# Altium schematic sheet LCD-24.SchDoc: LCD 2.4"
size A4; Date: Not used; ApprovedBy: Not used; CheckedBy: Not used; Author: Not used; CompanyName: STMicroelectronics; DrawnBy: Not used; Engineer: Not used; Organization: Not used; Address1: Not used; Address2: Not used; Address3: Not used; Address4: Not used; Revision: Not used; SheetNumber: 6; SheetTotal: 8
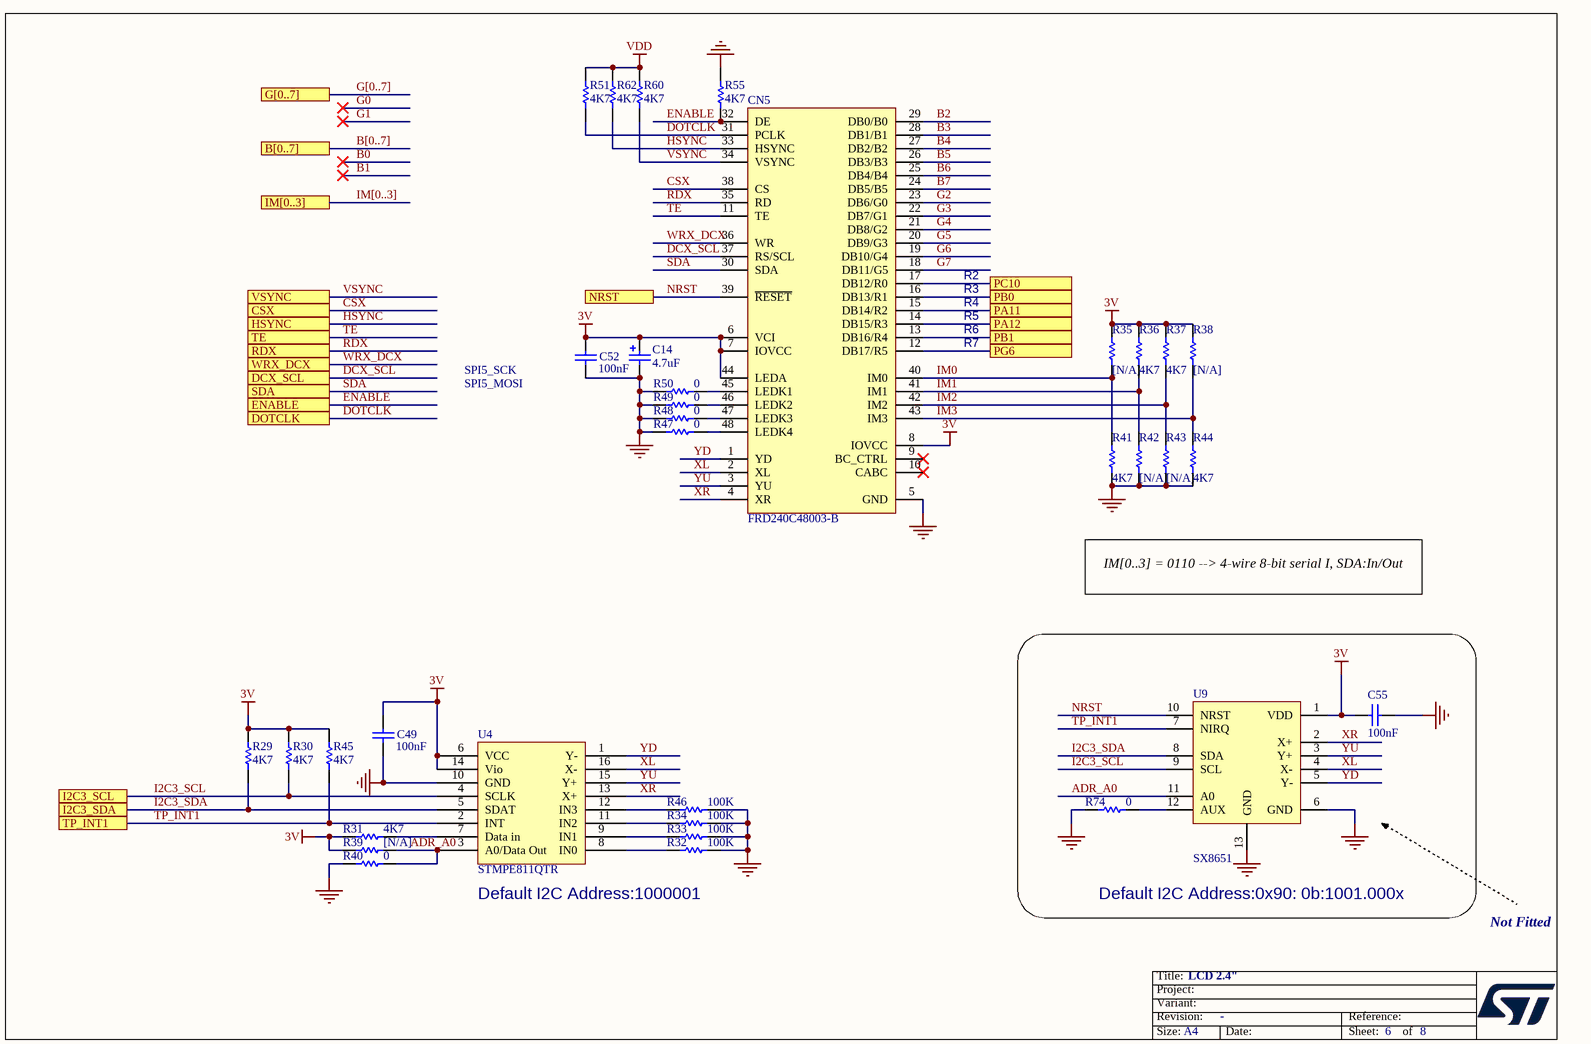
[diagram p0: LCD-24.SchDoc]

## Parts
C14  4.7uF  [TAN-A]
C49  100nF  [0402C]
C52  100nF  [0402C]
C55  100nF  [0402C]
CN5  FRD240C48003-B  [LCD_FRIDA_FRD240C48003-B]
R29  4K7  [0402R]
R30  4K7  [0402R]
R31  4K7  [0402R]
R32  100K  [0402R]
R33  100K  [0402R]
R34  100K  [0402R]
R35  [N/A]  [0402R]
R36  4K7  [0402R]
R37  4K7  [0402R]
R38  [N/A]  [0402R]
R39  [N/A]  [0402R]
R40  0  [0402R]
R41  4K7  [0402R]
R42  [N/A]  [0402R]
R43  [N/A]  [0402R]
R44  4K7  [0402R]
R45  4K7  [0402R]
R46  100K  [0402R]
R47  0  [0603R]
R48  0  [0603R]
R49  0  [0603R]
R50  0  [0603R]
R51  4K7  [0402R]
R55  4K7  [0402R]
R60  4K7  [0402R]
R62  4K7  [0402R]
R74  0  [0402R]
U4  STMPE811QTR  [QFN16_3X3]
U9  SX8651  [ICC_DFN12-EPAD_3X3_P045]

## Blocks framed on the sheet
Default I2C Address:0x90: 0b:1001.000x: C55 R74 U9

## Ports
B[0..7], CSX, DCX_SCL, DOTCLK, ENABLE, G[0..7], HSYNC, I2C3_SCL, I2C3_SDA, IM[0..3], NRST, PA11, PA12, PB0, PB1, PC10, PG6, RDX, SDA, TE, TP_INT1, VSYNC, WRX_DCX

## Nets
3V: C14.1 C49.2 C52.2 C55.1 CN5.6(VCI) CN5.7(IOVCC) CN5.8(IOVCC) CN5.44(LEDA) R29.2 R30.2 R31.1 R35.2 R36.2 R37.2 R38.2 R39.1 R45.2 U4.6(VCC) U4.14(Vio) U9.1(VDD)
GND: C14.2 C49.1 C52.1 C55.2 CN5.5(GND) R32.2 R33.2 R34.2 R40.1 R41.1 R42.1 R43.1 R44.1 R46.2 R47.1 R48.1 R49.1 R50.1 R55.2 R74.1 U4.10(GND) U9.6(GND) U9.13(GND)
VDD: R51.2 R60.2 R62.2
ADR_A0: R39.2 R40.2 U4.3(A0/Data_Out) U9.11(A0)
B2: CN5.29(DB0/B0)
B3: CN5.28(DB1/B1)
B4: CN5.27(DB2/B2)
B5: CN5.26(DB3/B3)
B6: CN5.25(DB4/B4)
B7: CN5.24(DB5/B5)
CSX: CN5.38(CS) ; port CSX
DCX_SCL: CN5.37(RS/SCL) ; port DCX_SCL
DOTCLK: CN5.31(PCLK) R51.1 ; port DOTCLK
ENABLE: CN5.32(DE) R55.1 ; port ENABLE
G2: CN5.23(DB6/G0)
G3: CN5.22(DB7/G1)
G4: CN5.21(DB8/G2)
G5: CN5.20(DB9/G3)
G6: CN5.19(DB10/G4)
G7: CN5.18(DB11/G5)
HSYNC: CN5.33(HSYNC) R62.1 ; port HSYNC
I2C3_SCL: R30.1 U4.4(SCLK) U9.9(SCL) ; port I2C3_SCL
I2C3_SDA: R29.1 U4.5(SDAT) U9.8(SDA) ; port I2C3_SDA
IM0: CN5.40(IM0) R35.1 R41.2
IM1: CN5.41(IM1) R36.1 R42.2
IM2: CN5.42(IM2) R37.1 R43.2
IM3: CN5.43(IM3) R38.1 R44.2
NRST: CN5.39(~{RESET}) U9.10(NRST) ; port NRST
PA11: CN5.15(DB14/R2) ; port PA11
PA12: CN5.14(DB15/R3) ; port PA12
PB0: CN5.16(DB13/R1) ; port PB0
PB1: CN5.13(DB16/R4) ; port PB1
PC10: CN5.17(DB12/R0) ; port PC10
PG6: CN5.12(DB17/R5) ; port PG6
RDX: CN5.35(RD) ; port RDX
SDA: CN5.30(SDA) ; port SDA
TE: CN5.11(TE) ; port TE
TP_INT1: R45.1 U4.2(INT) U9.7(NIRQ) ; port TP_INT1
VSYNC: CN5.34(VSYNC) R60.1 ; port VSYNC
WRX_DCX: CN5.36(WR) ; port WRX_DCX
XL: CN5.2(XL) U4.16(X-) U9.4(X-)
XR: CN5.4(XR) U4.13(X+) U9.2(X+)
YD: CN5.1(YD) U4.1(Y-) U9.5(Y-)
YU: CN5.3(YU) U4.15(Y+) U9.3(Y+)
NetCN5_45: CN5.45(LEDK1) R50.2
NetCN5_46: CN5.46(LEDK2) R49.2
NetCN5_47: CN5.47(LEDK3) R48.2
NetCN5_48: CN5.48(LEDK4) R47.2
NetR31_2: R31.2 U4.7(Data_in)
NetR32_1: R32.1 U4.8(IN0)
NetR33_1: R33.1 U4.9(IN1)
NetR34_1: R34.1 U4.11(IN2)
NetR46_1: R46.1 U4.12(IN3)
NetR74_2: R74.2 U9.12(AUX)

Not connected (* = marked no-connect by the designer): CN5 9(BC_CTRL)* 10(CABC)*

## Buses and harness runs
bus B[0..7] = port B[0..7]
bus G[0..7] = port G[0..7]
bus IM[0..3] = port IM[0..3]

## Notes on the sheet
- R4
- R5
- R3
- R2
- SPI5_MOSI
- SPI5_SCK
- R6
- R7
- IM[0..3] = 0110 --> 4-wire 8-bit serial I, SDA:In/Out
- Default I2C Address:1000001
- Not Fitted

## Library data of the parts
C14 = Cap Pol1: Polarized Capacitor (Radial); Value: 100pF
C49 C52 = Capacitor_ST: Capacitor 0402 / 0603 / 0805
C55 = Capacitor_ST: Capacitor 0402 / 0603 / 0805; Fitted: NO
CN5 = MCD-02110: TFT LCD 2.4inch 240RGB x 320 pixels + RTP; Part_Type: Display; Manufacturer: FRIDA SHENZEN LCD CO.LTD; ECCN_US: EAR99; ECCN_EU: NEC
R29-R34 R36 R37 R40 R41 R44-R51 R55 R60 R62 = Resistor_ST: Resistor 0402 / 0603 / 0805; Value: 10K
R35 R38 R39 R42 R43 R74 = Resistor_ST: Resistor 0402 / 0603 / 0805; Value: 10K; Fitted: NO
U4 = STMPE811: S-Touch® advanced resistive touchscreen controller, with 8-bit GPIO expander; Manuf_1: STM; Provided: ST; Ref St: xxxxxxxx; ECCN_US/EU: EAR99/NEC
U9 = MCD-01952: Multitouch 4-wire Resistive Touchscreen Controller with 15kV ESD Protection; Part_Type: IC; Manufacturer_Part_Number: SX8651IWLTRT; Manufacturer: SEMTECH; ECCN_US: EAR99; ECCN_EU: NEC; Provided_By: SUBCO; Fitted: NO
